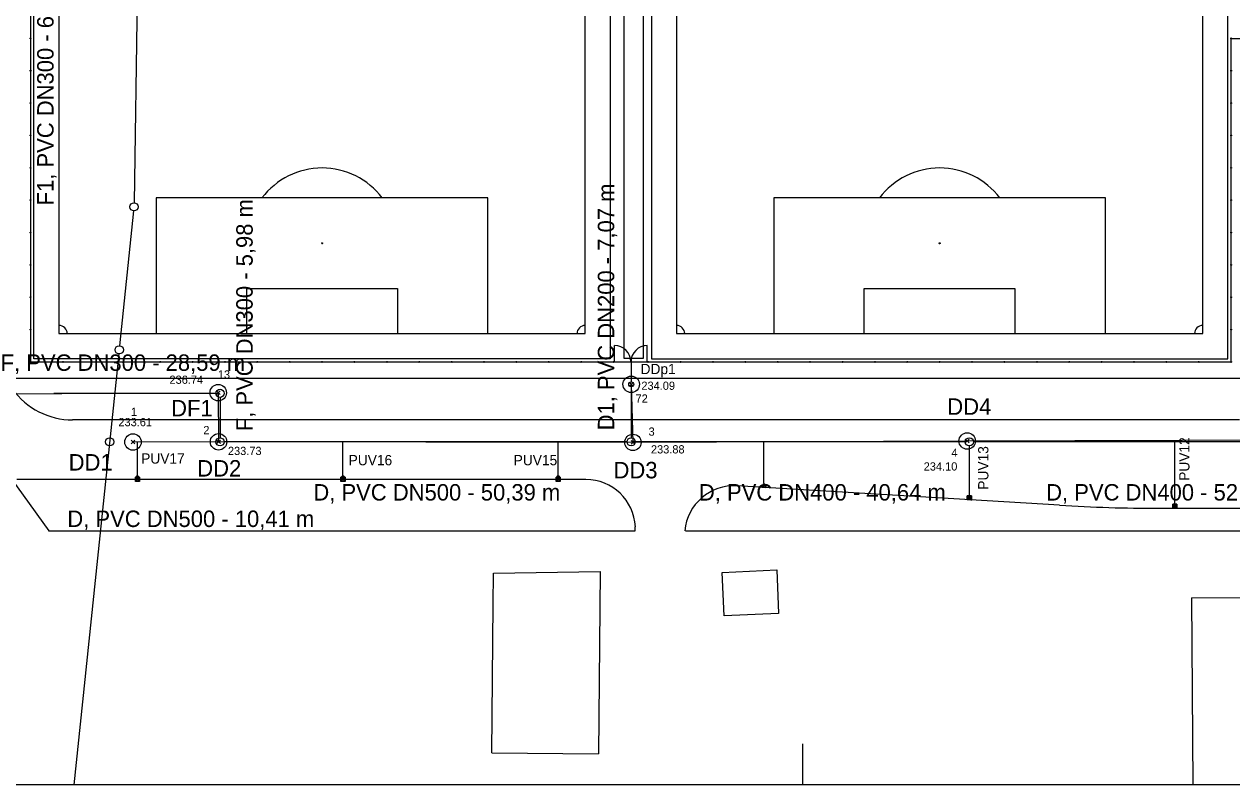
# Model space of a CAD drawing. Extents: x -264234 to -263604, y -1242346 to -1242049.
# Drawn here: x -264118.9 to -263972, y -1242345.9 to -1242253.3 of the extents above; entities that cross this region are included whole.
import ezdxf

# ---------------------------------------------------------------- set-up
doc = ezdxf.new("R2010")
doc.units = 0
for name, color, linetype in [('KFA_BODY_CISLO', 7, 'Continuous'), ('KFA_BODY_SYMBOL', 7, 'Continuous'), ('KFA_BODY_VYSKA', 7, 'Continuous'), ('KFA_DAZDOVA_KANALIZACIA_vetva_D', 7, 'Continuous'), ('KFA_DAZDOVA_KANALIZACIA_vetva_D_popis', 7, 'Continuous'), ('KFA_DAZDOVA_KANALIZACIA_vetva_F', 7, 'Continuous'), ('KFA_DAZDOVA_KANALIZACIA_vetva_F_popis', 7, 'Continuous'), ('KFA_JESTV_IS_DSP_-_KANAL_DAZD', 7, 'Continuous'), ('KFA_SITUACIA_DSP', 7, 'Continuous'), ('KFA_SO_40-2-II_DK_PRIPOJKY_UV_PROJEKT', 7, 'Continuous'), ('KFA_SO_40-2-II_DK_PRIPOJKY_UV_PROJEKT_popis', 7, 'Continuous'), ('KFA_SO_40-2-II_DK_UV_PROJEKT', 7, 'Continuous'), ('RAM_NA_TLAC_1-500', 7, 'Continuous')]:
    doc.layers.add(name, color=color, linetype=linetype)

msp = doc.modelspace()

# ---------------------------------------------------------------- linework, layer by layer
at = {"layer": 'KFA_BODY_SYMBOL'}
for p, q in [((-264045.25, -1242297.37), (-264044.81, -1242296.93)), ((-264044.81, -1242297.37), (-264045.25, -1242296.93)), ((-264095.47, -1242298.39), (-264095.03, -1242297.95)), ((-264095.03, -1242298.39), (-264095.47, -1242297.95)), ((-264105.84, -1242304.39), (-264105.4, -1242303.95)), ((-264105.4, -1242304.39), (-264105.84, -1242303.95)), ((-264095.43, -1242304.37), (-264094.99, -1242303.93)), ((-264094.99, -1242304.37), (-264095.43, -1242303.93)), ((-264045.04, -1242304.44), (-264044.6, -1242304)), ((-264044.6, -1242304.44), (-264045.04, -1242304)), ((-264004.4, -1242304.27), (-264003.95, -1242303.83)), ((-264003.95, -1242304.27), (-264004.4, -1242303.83))]:
    msp.add_line(p, q, dxfattribs=at)
at = {"layer": 'KFA_BODY_VYSKA'}
msp.add_line((-264105.62, -1242304.17), (-264105.62, -1242304.17), dxfattribs=at)
at = {"layer": 'KFA_DAZDOVA_KANALIZACIA_vetva_D'}
msp.add_line((-264045.03, -1242297.15), (-264044.82, -1242304.22), dxfattribs=at)
msp.add_lwpolyline([(-263821.59, -1242304.45), (-263853.82, -1242304.12), (-263903.79, -1242304.32), (-263951.83, -1242303.9), (-264004.17, -1242304.05), (-264044.82, -1242304.22), (-264095.21, -1242304.15), (-264105.62, -1242304.17)], dxfattribs=at)
for centre in [(-264045.03, -1242297.15), (-264105.62, -1242304.17), (-264095.21, -1242304.15), (-264044.82, -1242304.22), (-264004.17, -1242304.05)]:
    msp.add_circle(centre, 1, dxfattribs=at)
at = {"layer": 'KFA_DAZDOVA_KANALIZACIA_vetva_F'}
msp.add_lwpolyline([(-264123.84, -1242298.32), (-264095.25, -1242298.17), (-264095.21, -1242304.15)], dxfattribs=at)
msp.add_circle((-264095.25, -1242298.17), 1, dxfattribs=at)
at = {"layer": 'KFA_JESTV_IS_DSP_-_KANAL_DAZD'}
for p, q in [((-264104.23, -1242192.23), (-264105.48, -1242275.06)), ((-264105.54, -1242276.06), (-264107.24, -1242292.46)), ((-264107.35, -1242293.45), (-264112.79, -1242345.88))]:
    msp.add_line(p, q, dxfattribs=at)
for centre in [(-264105.49, -1242275.56), (-264107.29, -1242292.96)]:
    msp.add_circle(centre, 0.5, dxfattribs=at)
at = {"layer": 'KFA_SITUACIA_DSP'}
for p, q in [((-264118.07, -1242187.53), (-264118.07, -1242294.43)), ((-264204.69, -1242191.48), (-264115.87, -1242314.98)), ((-264114.62, -1242190.98), (-264114.62, -1242290.98)), ((-264050.62, -1242290.98), (-264050.62, -1242190.98)), ((-264039.52, -1242190.98), (-264039.52, -1242290.98)), ((-263975.52, -1242290.98), (-263975.52, -1242190.98)), ((-264045.93, -1242194.98), (-264045.93, -1242293.98)), ((-264043.53, -1242293.98), (-264043.53, -1242194.98)), ((-264118.07, -1242255.12), (-264118.07, -1242255)), ((-263972.07, -1242255.12), (-263972.07, -1242255)), ((-264118.01, -1242255.06), (-264118.13, -1242255.06)), ((-263972.13, -1242255.06), (-263972.01, -1242255.06)), ((-263972.07, -1242255.06), (-263967.42, -1242255.06)), ((-263972.07, -1242294.43), (-263972.07, -1242255.06)), ((-264118.01, -1242258.99), (-264118.13, -1242258.99)), ((-264118.07, -1242259.05), (-264118.07, -1242258.93)), ((-263972.13, -1242258.99), (-263972.01, -1242258.99)), ((-263972.07, -1242259.05), (-263972.07, -1242258.93)), ((-264118.01, -1242262.93), (-264118.13, -1242262.93)), ((-264118.07, -1242262.99), (-264118.07, -1242262.87)), ((-263972.13, -1242262.93), (-263972.01, -1242262.93)), ((-263972.07, -1242262.99), (-263972.07, -1242262.87)), ((-264118.01, -1242266.87), (-264118.13, -1242266.87)), ((-264118.07, -1242266.93), (-264118.07, -1242266.81)), ((-263972.13, -1242266.87), (-263972.01, -1242266.87)), ((-263972.07, -1242266.93), (-263972.07, -1242266.81)), ((-264118.01, -1242270.81), (-264118.13, -1242270.81)), ((-264118.07, -1242270.87), (-264118.07, -1242270.75)), ((-263972.13, -1242270.81), (-263972.01, -1242270.81)), ((-263972.07, -1242270.87), (-263972.07, -1242270.75)), ((-264118.01, -1242274.74), (-264118.13, -1242274.74)), ((-264118.07, -1242274.8), (-264118.07, -1242274.68)), ((-264062.46, -1242274.48), (-264102.78, -1242274.48)), ((-264102.78, -1242274.48), (-264102.78, -1242290.98)), ((-264062.46, -1242290.98), (-264062.46, -1242274.48)), ((-263987.36, -1242274.48), (-264027.68, -1242274.48)), ((-264027.68, -1242274.48), (-264027.68, -1242290.98)), ((-263987.36, -1242290.98), (-263987.36, -1242274.48)), ((-263972.13, -1242274.74), (-263972.01, -1242274.74)), ((-263972.07, -1242274.8), (-263972.07, -1242274.68)), ((-264118.01, -1242278.68), (-264118.13, -1242278.68)), ((-264118.07, -1242278.74), (-264118.07, -1242278.62)), ((-263972.13, -1242278.68), (-263972.01, -1242278.68)), ((-263972.07, -1242278.74), (-263972.07, -1242278.62)), ((-264118.01, -1242282.62), (-264118.13, -1242282.62)), ((-264118.07, -1242282.68), (-264118.07, -1242282.56)), ((-263972.13, -1242282.62), (-263972.01, -1242282.62)), ((-263972.07, -1242282.68), (-263972.07, -1242282.56)), ((-264091.78, -1242290.98), (-264091.78, -1242285.48)), ((-264091.78, -1242285.48), (-264073.46, -1242285.48)), ((-264073.46, -1242285.48), (-264073.46, -1242290.98)), ((-264016.68, -1242290.98), (-264016.68, -1242285.48)), ((-264016.68, -1242285.48), (-263998.36, -1242285.48)), ((-263998.36, -1242285.48), (-263998.36, -1242290.98)), ((-264118.01, -1242286.56), (-264118.13, -1242286.56)), ((-264118.07, -1242286.62), (-264118.07, -1242286.5)), ((-263972.13, -1242286.56), (-263972.01, -1242286.56)), ((-263972.07, -1242286.62), (-263972.07, -1242286.5)), ((-264118.01, -1242290.49), (-264118.13, -1242290.49)), ((-264118.07, -1242290.55), (-264118.07, -1242290.43)), ((-264114.62, -1242290.98), (-264050.62, -1242290.98)), ((-264039.52, -1242290.98), (-263975.52, -1242290.98)), ((-263972.13, -1242290.49), (-263972.01, -1242290.49)), ((-263972.07, -1242290.55), (-263972.07, -1242290.43)), ((-264047.07, -1242294.43), (-264047.07, -1242292.43)), ((-264043.07, -1242294.43), (-264043.07, -1242292.43)), ((-264118.01, -1242294.43), (-264118.13, -1242294.43)), ((-264118.07, -1242294.49), (-264118.07, -1242294.37)), ((-264118.07, -1242294.43), (-264045.12, -1242294.43)), ((-264114.07, -1242294.43), (-264114.19, -1242294.43)), ((-264114.13, -1242294.49), (-264114.13, -1242294.37)), ((-264102.25, -1242294.43), (-264102.37, -1242294.43)), ((-264102.31, -1242294.49), (-264102.31, -1242294.37)), ((-264098.31, -1242294.43), (-264098.43, -1242294.43)), ((-264098.37, -1242294.49), (-264098.37, -1242294.37)), ((-264094.37, -1242294.43), (-264094.49, -1242294.43)), ((-264094.43, -1242294.49), (-264094.43, -1242294.37)), ((-264090.44, -1242294.43), (-264090.56, -1242294.43)), ((-264090.5, -1242294.49), (-264090.5, -1242294.37)), ((-264086.5, -1242294.43), (-264086.62, -1242294.43)), ((-264086.56, -1242294.49), (-264086.56, -1242294.37)), ((-264082.56, -1242294.43), (-264082.68, -1242294.43)), ((-264082.62, -1242294.49), (-264082.62, -1242294.37)), ((-264078.62, -1242294.43), (-264078.74, -1242294.43)), ((-264078.68, -1242294.49), (-264078.68, -1242294.37)), ((-264074.68, -1242294.43), (-264074.8, -1242294.43)), ((-264074.74, -1242294.49), (-264074.74, -1242294.37)), ((-264070.74, -1242294.43), (-264070.86, -1242294.43)), ((-264070.8, -1242294.49), (-264070.8, -1242294.37)), ((-264066.8, -1242294.43), (-264066.92, -1242294.43)), ((-264066.86, -1242294.49), (-264066.86, -1242294.37)), ((-264062.86, -1242294.43), (-264062.98, -1242294.43)), ((-264062.92, -1242294.49), (-264062.92, -1242294.37)), ((-264058.92, -1242294.43), (-264059.04, -1242294.43)), ((-264058.98, -1242294.49), (-264058.98, -1242294.37)), ((-264054.99, -1242294.43), (-264055.11, -1242294.43)), ((-264055.05, -1242294.49), (-264055.05, -1242294.37)), ((-264051.05, -1242294.43), (-264051.17, -1242294.43)), ((-264051.11, -1242294.49), (-264051.11, -1242294.37)), ((-264047.11, -1242294.43), (-264047.23, -1242294.43)), ((-264047.17, -1242294.49), (-264047.17, -1242294.37)), ((-264045.93, -1242293.98), (-264043.53, -1242293.98)), ((-264045.57, -1242294.43), (-264044.57, -1242294.43)), ((-264045.12, -1242294.43), (-263972.07, -1242294.43)), ((-264045.02, -1242293.98), (-264045.03, -1242296.85)), ((-264042.91, -1242294.43), (-264043.03, -1242294.43)), ((-264042.97, -1242294.49), (-264042.97, -1242294.37)), ((-264038.97, -1242294.43), (-264039.09, -1242294.43)), ((-264039.03, -1242294.49), (-264039.03, -1242294.37)), ((-264035.03, -1242294.43), (-264035.15, -1242294.43)), ((-264035.09, -1242294.49), (-264035.09, -1242294.37)), ((-264031.09, -1242294.43), (-264031.21, -1242294.43)), ((-264031.15, -1242294.49), (-264031.15, -1242294.37)), ((-264027.15, -1242294.43), (-264027.27, -1242294.43)), ((-264027.21, -1242294.49), (-264027.21, -1242294.37)), ((-264023.21, -1242294.43), (-264023.33, -1242294.43)), ((-264023.27, -1242294.49), (-264023.27, -1242294.37)), ((-264019.27, -1242294.43), (-264019.39, -1242294.43)), ((-264019.33, -1242294.49), (-264019.33, -1242294.37)), ((-264015.34, -1242294.43), (-264015.46, -1242294.43)), ((-264015.4, -1242294.49), (-264015.4, -1242294.37)), ((-264011.4, -1242294.43), (-264011.52, -1242294.43)), ((-264011.46, -1242294.49), (-264011.46, -1242294.37)), ((-264007.46, -1242294.43), (-264007.58, -1242294.43)), ((-264007.52, -1242294.49), (-264007.52, -1242294.37)), ((-264003.52, -1242294.43), (-264003.64, -1242294.43)), ((-264003.58, -1242294.49), (-264003.58, -1242294.37)), ((-263999.58, -1242294.43), (-263999.7, -1242294.43)), ((-263999.64, -1242294.49), (-263999.64, -1242294.37)), ((-263995.64, -1242294.43), (-263995.76, -1242294.43)), ((-263995.7, -1242294.49), (-263995.7, -1242294.37)), ((-263991.7, -1242294.43), (-263991.82, -1242294.43)), ((-263991.76, -1242294.49), (-263991.76, -1242294.37)), ((-263987.76, -1242294.43), (-263987.88, -1242294.43)), ((-263987.82, -1242294.49), (-263987.82, -1242294.37)), ((-263983.82, -1242294.43), (-263983.94, -1242294.43)), ((-263983.88, -1242294.49), (-263983.88, -1242294.37)), ((-263979.89, -1242294.43), (-263980.01, -1242294.43)), ((-263979.95, -1242294.49), (-263979.95, -1242294.37)), ((-263975.95, -1242294.43), (-263976.07, -1242294.43)), ((-263976.01, -1242294.49), (-263976.01, -1242294.37)), ((-263972.13, -1242294.43), (-263972.01, -1242294.43)), ((-263972.07, -1242294.49), (-263972.07, -1242294.37)), ((-264045.03, -1242297.45), (-264045.03, -1242303.65)), ((-264115.25, -1242298.24), (-264095.53, -1242298.24)), ((-264095.03, -1242298.74), (-264095.03, -1242303.65)), ((-263971.07, -1242301.48), (-264112.96, -1242301.48)), ((-264105.08, -1242308.24), (-264105.08, -1242304.15)), ((-264045.53, -1242304.15), (-264094.53, -1242304.15)), ((-264080.08, -1242308.24), (-264080.08, -1242304.15)), ((-264053.91, -1242308.24), (-264053.91, -1242304.15)), ((-264004.4, -1242304.15), (-264044.53, -1242304.15)), ((-264028.9, -1242309.22), (-264028.89, -1242304.15)), ((-264003.9, -1242310.72), (-264003.9, -1242304.65)), ((-263954.41, -1242304.15), (-264003.4, -1242304.15)), ((-263978.91, -1242311.74), (-263978.91, -1242304.15)), ((-264050.53, -1242308.73), (-264119.75, -1242308.73)), ((-264105.33, -1242308.44), (-264104.83, -1242308.44)), ((-264105.33, -1242308.73), (-264105.33, -1242308.44)), ((-264105.33, -1242308.44), (-264104.83, -1242308.73)), ((-264105.33, -1242308.44), (-264104.83, -1242308.73)), ((-264104.83, -1242308.44), (-264105.33, -1242308.44)), ((-264104.83, -1242308.73), (-264105.33, -1242308.73)), ((-264104.83, -1242308.44), (-264104.83, -1242308.73)), ((-264104.83, -1242308.73), (-264104.83, -1242308.44)), ((-264080.33, -1242308.44), (-264079.83, -1242308.44)), ((-264080.33, -1242308.73), (-264080.33, -1242308.44)), ((-264080.33, -1242308.44), (-264079.83, -1242308.73)), ((-264080.33, -1242308.44), (-264079.83, -1242308.73)), ((-264079.83, -1242308.44), (-264080.33, -1242308.44)), ((-264079.83, -1242308.73), (-264080.33, -1242308.73)), ((-264079.83, -1242308.44), (-264079.83, -1242308.73)), ((-264079.83, -1242308.73), (-264079.83, -1242308.44)), ((-264054.16, -1242308.44), (-264053.66, -1242308.44)), ((-264054.16, -1242308.73), (-264054.16, -1242308.44)), ((-264054.16, -1242308.44), (-264053.66, -1242308.73)), ((-264054.16, -1242308.44), (-264053.66, -1242308.73)), ((-264053.66, -1242308.44), (-264054.16, -1242308.44)), ((-264053.66, -1242308.73), (-264054.16, -1242308.73)), ((-264053.66, -1242308.44), (-264053.66, -1242308.73)), ((-264053.66, -1242308.73), (-264053.66, -1242308.44)), ((-263992.94, -1242311.87), (-264032.17, -1242309.51)), ((-264032.17, -1242309.51), (-264032.17, -1242309.51)), ((-264029.16, -1242309.69), (-264029.14, -1242309.41)), ((-264028.66, -1242309.72), (-264029.16, -1242309.69)), ((-264029.14, -1242309.41), (-264028.65, -1242309.44)), ((-264029.14, -1242309.41), (-264028.66, -1242309.72)), ((-264029.14, -1242309.41), (-264028.66, -1242309.72)), ((-264028.65, -1242309.44), (-264029.14, -1242309.41)), ((-264028.65, -1242309.44), (-264028.66, -1242309.72)), ((-264028.66, -1242309.72), (-264028.65, -1242309.44)), ((-264004.16, -1242311.2), (-264004.15, -1242310.91)), ((-264003.66, -1242311.23), (-264004.16, -1242311.2)), ((-264004.15, -1242310.91), (-264003.65, -1242310.94)), ((-264004.15, -1242310.91), (-264003.66, -1242311.23)), ((-264004.15, -1242310.91), (-264003.66, -1242311.23)), ((-264003.65, -1242310.94), (-264004.15, -1242310.91)), ((-264003.65, -1242310.94), (-264003.66, -1242311.23)), ((-264003.66, -1242311.23), (-264003.65, -1242310.94)), ((-263980.94, -1242312.23), (-263857.33, -1242312.23)), ((-263979.16, -1242311.94), (-263978.66, -1242311.94)), ((-263979.16, -1242312.23), (-263979.16, -1242311.94)), ((-263979.16, -1242311.94), (-263978.66, -1242312.23)), ((-263979.16, -1242311.94), (-263978.66, -1242312.23)), ((-263978.66, -1242311.94), (-263979.16, -1242311.94)), ((-263978.66, -1242312.23), (-263979.16, -1242312.23)), ((-263978.66, -1242311.94), (-263978.66, -1242312.23)), ((-263978.66, -1242312.23), (-263978.66, -1242311.94)), ((-264115.89, -1242314.98), (-264044.53, -1242314.98)), ((-264044.53, -1242314.98), (-264044.53, -1242314.48)), ((-264038.44, -1242314.98), (-263836.4, -1242314.98)), ((-264061.82, -1242323.92), (-264061.79, -1242320.14)), ((-264061.79, -1242320.14), (-264048.82, -1242319.93)), ((-264048.82, -1242319.93), (-264048.99, -1242342.09)), ((-264033.95, -1242320.06), (-264027.34, -1242319.71)), ((-264033.72, -1242325.32), (-264033.95, -1242320.06)), ((-264027.34, -1242319.71), (-264027.11, -1242325.04)), ((-263976.89, -1242323.14), (-263880.39, -1242322.51)), ((-264061.96, -1242341.99), (-264061.82, -1242323.92)), ((-263976.89, -1242323.14), (-263976.74, -1242345.88)), ((-264027.11, -1242325.04), (-264033.72, -1242325.32)), ((-264061.96, -1242341.99), (-264048.99, -1242342.09))]:
    msp.add_line(p, q, dxfattribs=at)
for points in [[(-264117.67, -1242187.93), (-264047.57, -1242187.93), (-264047.57, -1242294.03), (-264117.67, -1242294.03)], [(-264042.57, -1242294.03), (-263972.47, -1242294.03), (-263972.47, -1242187.93), (-264042.57, -1242187.93)]]:
    msp.add_lwpolyline(points, close=True, dxfattribs=at)
msp.add_lwpolyline([(-263965.14, -1242296.43), (-264120.02, -1242296.43), (-264120.28, -1242296.43)], dxfattribs=at)
for centre, radius in [((-264118.07, -1242255.06), 0.06), ((-263972.07, -1242255.06), 0.06), ((-264118.07, -1242258.99), 0.06), ((-263972.07, -1242258.99), 0.06), ((-264118.07, -1242262.93), 0.06), ((-263972.07, -1242262.93), 0.06), ((-264118.07, -1242266.87), 0.06), ((-263972.07, -1242266.87), 0.06), ((-264118.07, -1242270.81), 0.06), ((-263972.07, -1242270.81), 0.06), ((-264118.07, -1242274.74), 0.06), ((-263972.07, -1242274.74), 0.06), ((-264118.07, -1242278.68), 0.06), ((-264082.62, -1242279.98), 0.06), ((-264007.52, -1242279.98), 0.06), ((-263972.07, -1242278.68), 0.06), ((-264118.07, -1242282.62), 0.06), ((-263972.07, -1242282.62), 0.06), ((-264118.07, -1242286.56), 0.06), ((-263972.07, -1242286.56), 0.06), ((-264118.07, -1242290.49), 0.06), ((-263972.07, -1242290.49), 0.06), ((-264118.07, -1242294.43), 0.06), ((-264114.13, -1242294.43), 0.06), ((-264102.31, -1242294.43), 0.06), ((-264098.37, -1242294.43), 0.06), ((-264094.43, -1242294.43), 0.06), ((-264090.5, -1242294.43), 0.06), ((-264086.56, -1242294.43), 0.06), ((-264082.62, -1242294.43), 0.06), ((-264078.68, -1242294.43), 0.06), ((-264074.74, -1242294.43), 0.06), ((-264070.8, -1242294.43), 0.06), ((-264066.86, -1242294.43), 0.06), ((-264062.92, -1242294.43), 0.06), ((-264058.98, -1242294.43), 0.06), ((-264055.05, -1242294.43), 0.06), ((-264051.11, -1242294.43), 0.06), ((-264047.17, -1242294.43), 0.06), ((-264042.97, -1242294.43), 0.06), ((-264039.03, -1242294.43), 0.06), ((-264035.09, -1242294.43), 0.06), ((-264031.15, -1242294.43), 0.06), ((-264027.21, -1242294.43), 0.06), ((-264023.27, -1242294.43), 0.06), ((-264019.33, -1242294.43), 0.06), ((-264015.4, -1242294.43), 0.06), ((-264011.46, -1242294.43), 0.06), ((-264007.52, -1242294.43), 0.06), ((-264003.58, -1242294.43), 0.06), ((-263999.64, -1242294.43), 0.06), ((-263995.7, -1242294.43), 0.06), ((-263991.76, -1242294.43), 0.06), ((-263987.82, -1242294.43), 0.06), ((-263983.88, -1242294.43), 0.06), ((-263979.95, -1242294.43), 0.06), ((-263976.01, -1242294.43), 0.06), ((-263972.07, -1242294.43), 0.06), ((-264045.03, -1242297.15), 0.3), ((-264095.03, -1242298.24), 0.5), ((-264108.46, -1242304.15), 0.5), ((-264095.03, -1242304.15), 0.5), ((-264045.03, -1242304.15), 0.5), ((-264003.9, -1242304.15), 0.5), ((-264105.08, -1242308.34), 0.1), ((-264080.08, -1242308.34), 0.1), ((-264053.91, -1242308.34), 0.1), ((-264028.89, -1242309.32), 0.1), ((-264003.9, -1242310.82), 0.1), ((-263978.91, -1242311.84), 0.1)]:
    msp.add_circle(centre, radius, dxfattribs=at)
for centre, radius, start, end in [((-264082.62, -1242279.98), 9.15, 36.9482, 143.0518), ((-264007.52, -1242279.98), 9.15, 36.9482, 143.0518), ((-264082.62, -1242279.98), 0.0303, 90, 270), ((-264082.62, -1242279.98), 0.0303, 270, 90), ((-264007.52, -1242279.98), 0.0303, 90, 270), ((-264007.52, -1242279.98), 0.0303, 270, 90), ((-264114.62, -1242290.98), 1, 0, 90), ((-264050.62, -1242290.98), 1, 90, 180), ((-264039.52, -1242290.98), 1, 0, 90), ((-263975.52, -1242290.98), 1, 90, 180), ((-264047.07, -1242294.43), 2, 0, 90), ((-264043.07, -1242294.43), 2, 90, 180), ((-264112.96, -1242292.48), 9, 215.724, 270), ((-264050.56, -1242314.77), 6.04, 2.7254, 89.7124), ((-264032.53, -1242315.5), 6, 86.5602, 175.0205), ((-263980.94, -1242112.23), 200, 266.5602, 270)]:
    msp.add_arc(centre, radius, start, end, dxfattribs=at)
at = {"layer": 'KFA_SO_40-2-II_DK_PRIPOJKY_UV_PROJEKT'}
for points in [[(-264105.08, -1242308.24), (-264105.08, -1242304.15)], [(-264080.08, -1242308.24), (-264080.08, -1242304.15)], [(-264053.91, -1242308.24), (-264053.91, -1242304.15)], [(-264003.9, -1242310.72), (-264003.9, -1242304.65)], [(-263978.91, -1242311.74), (-263978.91, -1242304.15)]]:
    msp.add_lwpolyline(points, dxfattribs=at)
at = {"layer": 'KFA_SO_40-2-II_DK_UV_PROJEKT'}
for points in [[(-264105.33, -1242308.98), (-264105.33, -1242308.48), (-264104.83, -1242308.48), (-264104.83, -1242308.98), (-264105.33, -1242308.98), (-264104.83, -1242308.48), (-264105.33, -1242308.48), (-264104.83, -1242308.98)], [(-264080.33, -1242308.98), (-264080.33, -1242308.48), (-264079.83, -1242308.48), (-264079.83, -1242308.98), (-264080.33, -1242308.98), (-264079.83, -1242308.48), (-264080.33, -1242308.48), (-264079.83, -1242308.98)], [(-264054.16, -1242308.98), (-264054.16, -1242308.48), (-264053.66, -1242308.48), (-264053.66, -1242308.98), (-264054.16, -1242308.98), (-264053.66, -1242308.48), (-264054.16, -1242308.48), (-264053.66, -1242308.98)], [(-264004.16, -1242311.2), (-264004.16, -1242310.7), (-264003.66, -1242310.7), (-264003.66, -1242311.2), (-264004.16, -1242311.2), (-264003.66, -1242310.7), (-264004.16, -1242310.7), (-264003.66, -1242311.2)], [(-263979.16, -1242312.23), (-263979.16, -1242311.73), (-263978.66, -1242311.73), (-263978.66, -1242312.23), (-263979.16, -1242312.23), (-263978.66, -1242311.73), (-263979.16, -1242311.73), (-263978.66, -1242312.23)]]:
    msp.add_lwpolyline(points, dxfattribs=at)
at = {"layer": 'RAM_NA_TLAC_1-500'}
msp.add_line((-264024.18, -1242340.88), (-264024.18, -1242345.88), dxfattribs=at)
msp.add_lwpolyline([(-264234.18, -1242048.88), (-263604.18, -1242048.88), (-263604.18, -1242345.88), (-264234.18, -1242345.88)], close=True, dxfattribs=at)

# ---------------------------------------------------------------- texts
at = {"layer": 'KFA_BODY_CISLO'}
for s, p in [('13', (-264095.3, -1242296.46)), ('72', (-264044.5, -1242299.38)), ('1', (-264105.86, -1242300.99)), ('2', (-264097.06, -1242303.22)), ('3', (-264042.92, -1242303.4)), ('4', (-264006.09, -1242305.96))]:
    msp.add_text(s, height=1, dxfattribs=at).set_placement(p)
at = {"layer": 'KFA_BODY_VYSKA'}
for s, p in [('236.74', (-264101.18, -1242297.09)), ('234.09', (-264043.79, -1242297.82)), ('233.61', (-264107.39, -1242302.25)), ('233.73', (-264094.07, -1242305.75)), ('233.88', (-264042.63, -1242305.56)), ('234.10', (-264009.46, -1242307.64))]:
    msp.add_text(s, height=1, dxfattribs=at).set_placement(p)
at = {"layer": 'KFA_DAZDOVA_KANALIZACIA_vetva_D_popis'}
msp.add_text('D1, PVC DN200 - 7,07 m', height=2, rotation=90, dxfattribs=at).set_placement((-264047.09, -1242302.75))
for s, height, p in [('DDp1', 1.25, (-264043.89, -1242295.91)), ('DD4', 2, (-264006.59, -1242300.86)), ('DD1', 2, (-264113.44, -1242307.64)), ('DD2', 2, (-264097.8, -1242308.37)), ('DD3', 2, (-264047.18, -1242308.59)), ('D, PVC DN500 - 50,39 m', 2, (-264083.68, -1242311.29)), ('D, PVC DN400 - 40,64 m', 2, (-264036.8, -1242311.29)), ('D, PVC DN400 - 52,34 m', 2, (-263994.57, -1242311.29)), ('D, PVC DN500 - 10,41 m', 2, (-264113.6, -1242314.51))]:
    msp.add_text(s, height=height, dxfattribs=at).set_placement(p)
at = {"layer": 'KFA_DAZDOVA_KANALIZACIA_vetva_F_popis'}
for s, p in [('F1, PVC DN300 - 60,90 m', (-264115.27, -1242275.38)), ('F, PVC DN300 - 5,98 m', (-264091.06, -1242302.86))]:
    msp.add_text(s, height=2, rotation=90, dxfattribs=at).set_placement(p)
for s, p in [('F, PVC DN300 - 28,59 m', (-264121.71, -1242295.51)), ('DF1', (-264100.98, -1242301.05))]:
    msp.add_text(s, height=2, dxfattribs=at).set_placement(p)
at = {"layer": 'KFA_SO_40-2-II_DK_PRIPOJKY_UV_PROJEKT_popis'}
for s, p in [('PUV13', (-264001.59, -1242309.97)), ('PUV12', (-263977.14, -1242308.89))]:
    msp.add_text(s, height=1.25, rotation=90, dxfattribs=at).set_placement(p)
for s, p in [('PUV17', (-264104.62, -1242306.8)), ('PUV16', (-264079.39, -1242307)), ('PUV15', (-264059.32, -1242307))]:
    msp.add_text(s, height=1.25, dxfattribs=at).set_placement(p)

doc.saveas('drawing.dxf')
